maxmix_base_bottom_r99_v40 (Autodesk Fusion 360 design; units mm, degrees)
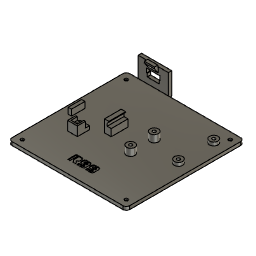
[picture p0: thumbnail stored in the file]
parameter "M2_SELF_TAP" = 1.85 comment "Hole size for self tapping M2"
sketch "Sketch1" plane through (0, 0, 0) normal (0, 0, 1) x axis (1, 0, 0)
  line L1 (33, 35) -> (-33, 35)
  line L2 (35, -33) -> (35, 33)
  line L3 (-33, -35) -> (33, -35)
  line L4 (-35, 33) -> (-35, -33)
  line L5 (0, 35) -> (0, -35)
  line L6 (35, 0) -> (-35, 0)
  arc A1 centre (-33, 33) radius 2 clockwise from (-35, 33) to (-33, 35)
  arc A2 centre (-33, -33) radius 2 clockwise from (-33, -35) to (-35, -33)
  arc A3 centre (33, -33) radius 2 clockwise from (35, -33) to (33, -35)
  arc A4 centre (33, 33) radius 2 clockwise from (33, 35) to (35, 33)
  point P2 (-35, 35)
  point P4 (-35, -35)
  point P3 (35, 35)
  point P17 (0, -35)
  point P18 (0, 35)
  point P19 (-35, 0)
  point P20 (35, 0)
  point P1 (0, 0)
  horizontal L1
  vertical L2
  horizontal L3
  vertical L4
  coincident P2 L1
  coincident P2 L4
  tangent L1 A1
  tangent L4 A1
  coincident P4 L4
  coincident P4 L3
  tangent L4 A2
  tangent L3 A2
  equal A1 A2
  tangent L3 A3
  tangent L2 A3
  equal A1 A3
  coincident P3 L1
  coincident P3 L2
  tangent L1 A4
  tangent L2 A4
  equal A1 A4
  midpoint L3 P17
  midpoint L1 P18
  midpoint L4 P19
  midpoint L2 P20
  coincident P1 L5
  coincident P1 L6
  dimension "d4" distance P2 P3 = 70
  dimension "d5" distance P2 P4 = 70
  dimension "d6" radius A1 = 2
extrude "Extrude1" new body sketch "Sketch1" profile of L1 L2 L3 L4 A1 A2 A3 A4 against normal blind 2
sketch "Sketch3" plane through (0, 0, -2) normal (0, 0, -1) x axis (1, 0, 0)
  line L1 (-33, 35) -> (33, 35)
  line L2 (-35, -33) -> (-35, 33)
  line L3 (33, -35) -> (-33, -35)
  line L4 (35, 33) -> (35, -33)
  line L5 (-30.9, -30.9) -> (30.9, -30.9)
  line L6 (-30.9, 30.9) -> (-30.9, -30.9)
  line L7 (30.9, 30.9) -> (-30.9, 30.9)
  line L8 (30.9, -30.9) -> (30.9, 30.9)
  line L9 (-30.9, 30.9) -> (30.9, -30.9)
  line L10 (30.9, 30.9) -> (-30.9, -30.9)
  arc A1 centre (33, 33) radius 2 clockwise from (33, 35) to (35, 33)
  arc A2 centre (-33, 33) radius 2 clockwise from (-35, 33) to (-33, 35)
  arc A3 centre (-33, -33) radius 2 clockwise from (-33, -35) to (-35, -33)
  arc A4 centre (33, -33) radius 2 clockwise from (35, -33) to (33, -35)
  point P18 (0, 0)
  point P1 (0, 0)
  point P16 (-30.9, 30.9)
  point P19 (-30.9, 30.9)
  point P17 (30.9, 30.9)
  point P20 (30.9, 30.9)
  point P14 (30.9, -30.9)
  point P21 (30.9, -30.9)
  point P15 (-30.9, -30.9)
  point P22 (-30.9, -30.9)
  horizontal L5
  perpendicular L5 L6
  parallel L5 L7
  parallel L6 L8
  coincident L9 P18
  coincident L10 P18
  coincident P1 P18
  coincident P16 P19
  coincident P17 P20
  coincident P14 P21
  coincident P15 P22
  dimension "d17" distance P16 P17 = 61.8
  dimension "d18" distance P15 P16 = 61.8
hole "Hole1" HoleDepth 2 HoleDiameter 2 TipAngle 118 CSDiameter 4.5 CSAngle 90
work_plane "WorkPlane1" AlongDistance -10
sketch "Sketch2" plane through (-10, 0, 0) normal (1, 0, 0) x axis (0, 1, 0)
  line L1 (35, -2) -> (35, 0)
  line L2 (35, 0) -> (35, -2)
  line L3 (35, 12) -> (35, 0)
  line L4 (37, 12) -> (35, 12)
  line L5 (37, -1) -> (37, 12)
  line L6 (36, -2) -> (37, -1)
  line L7 (35, -2) -> (36, -2)
  point P2 (35, 0)
  point P4 (35, 0)
  point P3 (35, -2)
  point P9 (35, -2)
  point P5 (35, 12)
  point P6 (37, 12)
  point P8 (36, -2)
  coincident P2 P4
  parallel L1 L3
  perpendicular L3 L4
  perpendicular L4 L5
  coincident P3 P9
  perpendicular L1 L7
  dimension "d10" distance P5 P6 = 2
  dimension "d11" distance P4 L4 = 12
  dimension "d12" angle L6 L7 = 45
  dimension "d13" distance L5 P8 = 1
extrude "Extrude2" add sketch "Sketch2" against normal blind 18
work_plane "WorkPlane2"
sketch "Sketch14" plane through (-19, 36, 5) normal (-1, 0, 0) x axis (0, 1, 0)
  line L1 (1, -7) -> (-1, -7)
  line L2 (-1, -7) -> (-1, 5)
  line L3 (-3.25, -7) -> (-1, -3.7867)
  line L4 (-3.25, -8) -> (-3.25, -7)
  line L5 (-1.25, -8) -> (-3.25, -8)
  line L6 (-1.25, -7) -> (-1.25, -8)
  line L7 (-1, -7) -> (-1.25, -7)
  point P5 (-1, -3.7867)
  point P2 (-1, -7)
  point P10 (-1, -7)
  point P6 (-3.25, -7)
  point P7 (-3.25, -8)
  point P8 (-1.25, -8)
  coincident L2 P5
  parallel L2 L4
  perpendicular L4 L5
  perpendicular L1 L6
  coincident P2 P10
  perpendicular L6 L7
  coincident P6 L7
  dimension "d109" = 3
  dimension "d110" distance P7 P8 = 2
  dimension "d111" distance P6 P7 = 1
  dimension "d112" distance L6 P10 = 0.25
  dimension "d115" angle L2 L3 = 35
extrude "Extrude18" add sketch "Sketch14" profile of L2 L3 L4 L5 L6 L7 distance 3
sketch "Sketch4" plane through (0, 37, 0) normal (0, 1, 0) x axis (-1, 0, 0)
  line L1 (10, -1) -> (10, 12)
  line L2 (28, -1) -> (10, -1)
  line L3 (28, 12) -> (28, -1)
  line L4 (10, 12) -> (28, 12)
  line L5 (10, -1) -> (10, 12)
  line L6 (10, -2) -> (10, -1)
  line L7 (28, -2) -> (10, -2)
  line L8 (28, -2) -> (28, -1)
  line L9 (28, -1) -> (28, 12)
  line L10 (28, 12) -> (10, 12)
  line L11 (15.025, 5.375) -> (15.025, 7.85)
  line L12 (15.425, 5.375) -> (15.025, 5.375)
  line L13 (15.425, 3.5) -> (15.425, 5.375)
  line L14 (22.575, 3.5) -> (15.425, 3.5)
  line L15 (22.575, 5.375) -> (22.575, 3.5)
  line L16 (22.975, 5.375) -> (22.575, 5.375)
  line L17 (22.975, 7.85) -> (22.975, 5.375)
  line L18 (15.025, 7.85) -> (22.975, 7.85)
  line L19 (19, 12) -> (19, -2)
  line L20 (10, 0) -> (28, 0)
  point P20 (19, -2)
  point P21 (19, 12)
  point P12 (15.025, 7.85)
  point P19 (22.975, 7.85)
  point P15 (15.425, 3.5)
  point P16 (22.575, 3.5)
  vertical L11
  perpendicular L11 L12
  perpendicular L12 L13
  perpendicular L13 L14
  perpendicular L14 L15
  perpendicular L15 L16
  perpendicular L16 L17
  perpendicular L11 L18
  midpoint L7 P20
  midpoint L10 P21
  symmetric L11 L17 L19
  symmetric L13 L15 L19
  collinear L12 L16
  dimension "d26" distance P12 P19 = 7.95
  dimension "d27" distance P15 P16 = 7.15
  dimension "d29" distance L14 L18 = 4.35
  dimension "d30" distance L12 L18 = 2.475
  dimension "d102" distance L14 L20 = 3.5
extrude "Extrude3" cut sketch "Sketch4" profile of L11 L12 L13 L14 L15 L16 L17 L18 no distance stored
sketch "Sketch5" plane through (0, 0, 0) normal (0, 0, 1) x axis (-1, 0, 0)
  line L1 (-35, -33) -> (-35, 33)
  line L2 (10, -35) -> (-33, -35)
  line L3 (28, -35) -> (10, -35)
  line L4 (33, -35) -> (28, -35)
  line L5 (35, 33) -> (35, -33)
  line L6 (-33, 35) -> (33, 35)
  line L7 (-27.5, -3.5) -> (-27.5, -24.5)
  circle C1 centre (-30.9, 30.9) radius 1
  circle C2 centre (30.9, -30.9) radius 1
  circle C3 centre (-30.9, -30.9) radius 1
  circle C4 centre (30.9, 30.9) radius 1
  arc A1 centre (-33, 33) radius 2 clockwise from (-35, 33) to (-33, 35)
  arc A2 centre (-33, -33) radius 2 clockwise from (-33, -35) to (-35, -33)
  arc A3 centre (33, -33) radius 2 clockwise from (35, -33) to (33, -35)
  arc A4 centre (33, 33) radius 2 clockwise from (33, 35) to (35, 33)
  circle C5 centre (-27.5, -24.5) radius 2.5
  circle C6 centre (-27.5, -3.5) radius 2.5
  circle C7 centre (-27.5, -3.5) radius 0.925
  circle C8 centre (-27.5, -24.5) radius 0.925
  point P20 (-27.5, -24.5)
  point P22 (-27.5, -24.5)
  point P21 (-27.5, -3.5)
  point P23 (-27.5, -3.5)
  point P1 (0, 0)
  vertical L7
  coincident P20 P22
  coincident P21 P23
  equal C5 C6
  concentric C6 C7
  concentric C5 C8
  equal C7 C8
  dimension "d32" distance P1 L7 = 27.5
  dimension "d33" distance P20 P21 = 21
  dimension "d34" distance P1 P21 = 3.5
  dimension "d35" diameter C6 = 5
  dimension "d36" diameter C7 = 1.85 (= "M2_SELF_TAP")
extrude "Extrude4" add sketch "Sketch5" profile of C5 C6 C7 C8 along normal blind 2
sketch "Sketch6" plane through (0, 0, 0) normal (0, 0, 1) x axis (-1, 0, 0)
  line L1 (-35, -33) -> (-35, 33)
  line L2 (10, -35) -> (-33, -35)
  line L3 (28, -35) -> (10, -35)
  line L4 (33, -35) -> (28, -35)
  line L5 (35, 33) -> (35, -33)
  line L6 (-33, 35) -> (33, 35)
  line L7 (28.4, -3.8) -> (30.4, -3.8)
  line L8 (28.4, 4.2) -> (28.4, -3.8)
  line L9 (30.4, 4.2) -> (28.4, 4.2)
  line L10 (30.4, -3.8) -> (30.4, 4.2)
  line L11 (10, -7) -> (6, -7)
  line L12 (10, 3) -> (10, -7)
  line L13 (6, 3) -> (10, 3)
  line L14 (6, -7) -> (6, 3)
  line L15 (16.1, 5.8) -> (21.9, 5.8)
  line L16 (16.1, 13) -> (16.1, 5.8)
  line L17 (21.9, 13) -> (16.1, 13)
  line L18 (21.9, 5.8) -> (21.9, 13)
  line L19 (16.1, 8.2) -> (21.9, 8.2)
  line L20 (20.9, 12) -> (20.9, 8.2)
  line L21 (17.1, 12) -> (20.9, 12)
  line L22 (17.1, 8.2) -> (17.1, 12)
  line L23 (17.1, 10.1) -> (20.9, 10.1)
  line L24 (19, 12) -> (19, 8.2)
  circle C1 centre (-27.5, -3.5) radius 2.5
  circle C2 centre (-30.9, 30.9) radius 1
  circle C3 centre (30.9, -30.9) radius 1
  circle C4 centre (-30.9, -30.9) radius 1
  circle C5 centre (30.9, 30.9) radius 1
  arc A1 centre (-33, 33) radius 2 clockwise from (-35, 33) to (-33, 35)
  arc A2 centre (-33, -33) radius 2 clockwise from (-33, -35) to (-35, -33)
  arc A3 centre (33, -33) radius 2 clockwise from (35, -33) to (33, -35)
  arc A4 centre (33, 33) radius 2 clockwise from (33, 35) to (35, 33)
  circle C6 centre (-27.5, -24.5) radius 2.5
  circle C7 centre (19, 10.1) radius 0.925
  point P34 (21.9, 8.2)
  point P35 (16.1, 8.2)
  point P36 (20.9, 8.2)
  point P39 (17.1, 8.2)
  point P40 (20.9, 10.1)
  point P41 (17.1, 10.1)
  point P42 (19, 8.2)
  point P43 (19, 12)
  point P44 (19, 10.1)
  point P1 (0, 0)
  point P24 (28.4, 4.2)
  point P22 (30.4, -3.8)
  point P23 (28.4, -3.8)
  point P25 (30.4, 4.2)
  point P26 (6, -7)
  point P27 (10, -7)
  point P28 (10, 3)
  point P32 (16.1, 13)
  point P33 (21.9, 13)
  point P30 (21.9, 5.8)
  horizontal L7
  vertical L8
  horizontal L9
  vertical L10
  horizontal L11
  vertical L12
  horizontal L13
  vertical L14
  horizontal L15
  vertical L16
  horizontal L17
  vertical L18
  coincident L18 P34
  coincident L16 P35
  perpendicular L16 L19
  coincident L19 P36
  perpendicular L19 L20
  perpendicular L20 L21
  coincident L19 P39
  perpendicular L19 L22
  midpoint L20 P40
  midpoint L22 P41
  midpoint L19 P42
  midpoint L21 P43
  midpoint L23 P44
  dimension "d39" distance P1 P24 = 28.4
  dimension "d40" distance P1 P24 = 4.2
  dimension "d41" distance P22 P23 = 2
  dimension "d42" distance P22 P25 = 8
  dimension "d43" distance P1 L14 = 6
  dimension "d44" distance P1 P26 = 7
  dimension "d45" distance P26 P27 = 4
  dimension "d46" distance P27 P28 = 10
  dimension "d47" distance P1 L16 = 16.1
  dimension "d48" distance P1 L15 = 5.8
  dimension "d49" distance P32 P33 = 5.8
  dimension "d50" distance P30 P33 = 7.2
  dimension "d51" distance L15 L19 = 2.4
  dimension "d52" distance L16 L22 = 1
  dimension "d53" distance L18 L20 = 1 (= "d52")
  dimension "d54" distance L17 L21 = 1 (= "d52")
  dimension "d55" diameter C7 = 1.85 (= "M2_SELF_TAP")
  dimension "d124" distance L8 L12 = 18.4
extrude "Extrude5" add sketch "Sketch6" profile of L7 L8 L9 L10 L11 L12 L13 L14 along normal blind 3.6
extrude "Extrude6" add sketch "Sketch6" profile of L11 L13 L14 L15 L16 L18 L19 along normal blind 2
extrude "Extrude7" add sketch "Sketch6" profile of L19 L20 L21 L22 C7 along normal blind 3.5
extrude "Extrude8" add sketch "Sketch6" profile of L16 L17 L18 L19 L20 L21 L22 along normal blind 5.5
sketch "Sketch7" plane through (0, 0, 0) normal (0, 0, 1) x axis (-1, 0, 0)
  line L1 (16.1, 13) -> (16.1, 5.8)
  line L2 (21.9, 13) -> (16.1, 13)
  line L3 (21.9, 5.8) -> (21.9, 13)
  line L4 (16.1, 5.8) -> (21.9, 5.8)
  line L5 (-35, -33) -> (-35, 33)
  line L6 (10, -35) -> (-33, -35)
  line L7 (28, -35) -> (10, -35)
  line L8 (33, -35) -> (28, -35)
  line L9 (35, 33) -> (35, -33)
  line L10 (-33, 35) -> (33, 35)
  line L11 (30.4, -3.8) -> (30.4, 4.2)
  line L12 (28.4, -3.8) -> (30.4, -3.8)
  line L13 (28.4, 4.2) -> (28.4, -3.8)
  line L14 (30.4, 4.2) -> (28.4, 4.2)
  line L15 (6, -7) -> (10, -7)
  line L16 (6, 3) -> (6, -7)
  line L17 (10, 3) -> (6, 3)
  line L18 (10, -7) -> (10, 3)
  line L19 (-8.65, 6.5) -> (-8.65, -10.5)
  line L20 (6, -7) -> (6, 3)
  line L21 (10, -7) -> (6, -7)
  line L22 (10, 3) -> (10, -7)
  line L23 (6, 3) -> (10, 3)
  line L24 (8.25, 3) -> (8.25, -7)
  circle C1 centre (-27.5, -24.5) radius 2.5
  arc A1 centre (-33, 33) radius 2 clockwise from (-35, 33) to (-33, 35)
  arc A2 centre (-33, -33) radius 2 clockwise from (-33, -35) to (-35, -33)
  arc A3 centre (33, -33) radius 2 clockwise from (35, -33) to (33, -35)
  arc A4 centre (33, 33) radius 2 clockwise from (33, 35) to (35, 33)
  circle C2 centre (30.9, 30.9) radius 1
  circle C3 centre (-30.9, -30.9) radius 1
  circle C4 centre (30.9, -30.9) radius 1
  circle C5 centre (-30.9, 30.9) radius 1
  circle C6 centre (-27.5, -3.5) radius 2.5
  circle C7 centre (-8.65, -10.5) radius 2.5
  circle C8 centre (-8.65, 6.5) radius 2.5
  circle C9 centre (-8.65, -10.5) radius 0.925
  circle C10 centre (-8.65, 6.5) radius 0.925
  point P34 (-8.65, -10.5)
  point P38 (-8.65, -10.5)
  point P37 (-8.65, 6.5)
  point P39 (-8.65, 6.5)
  point P44 (8.25, -7)
  point P45 (8.25, 3)
  point P1 (0, 0)
  point P36 (-8.65, -10.5)
  equal C7 C8
  concentric C7 C9
  concentric C8 C10
  equal C9 C10
  coincident P34 P38
  coincident P37 P39
  vertical L19
  coincident L15 P44
  coincident L17 P45
  perpendicular L17 L24
  dimension "d65" distance P1 P34 = 10.5
  dimension "d67" diameter C7 = 5
  dimension "d68" diameter C9 = 1.85 (= "M2_SELF_TAP")
  dimension "d72" distance P36 P37 = 17
  dimension "d73" distance P1 L19 = 8.65
  dimension "d127" distance P36 L24 = 16.9
extrude "Extrude9" add sketch "Sketch7" profile of C7 C8 C9 C10 along normal blind 2
extrude "Extrude19" sketch "Sketch7" profile of L15 L16 L17 L20 L21 L23 L24 no distance stored
sketch "Sketch20" plane through (0, -3, 0) normal (0, -1, 0) x axis (1, 0, 0)
  line L1 (-8.25, 2) -> (-6, 2)
  line L2 (-8.25, 3.6) -> (-8.25, 2)
  line L3 (-10, 3.6) -> (-8.25, 3.6)
  line L4 (-10, 0) -> (-10, 3.6)
  line L5 (-6, 0) -> (-10, 0)
  line L6 (-6, 2) -> (-6, 0)
  line L7 (-8.25, 3.6) -> (-10, 3.6)
  line L8 (-7.25, 4.6) -> (-8.25, 3.6)
  line L9 (-10, 3.6) -> (-10, 5)
  line L10 (-7.25, 5) -> (-7.25, 4.6)
  line L11 (-10, 5) -> (-7.25, 5)
  point P4 (-8.25, 3.6)
  point P10 (-8.25, 3.6)
  point P8 (-10, 3.6)
  point P13 (-10, 3.6)
  point P12 (-10, 5)
  point P15 (-10, 5)
  point P11 (-7.25, 4.6)
  coincident P4 P10
  coincident P8 P13
  vertical L9
  vertical L10
  perpendicular L10 L11
  coincident P12 P15
  dimension "d135" angle L7 L8 = 135
  dimension "d140" distance P10 P11 = 1
  dimension "d141" distance P11 L11 = 0.4
extrude "Extrude21" add sketch "Sketch20" profile of L3 L7 L8 L9 to an object
sketch "Sketch9" plane through (0, 0, 0) normal (0, 0, 1) x axis (1, 0, 0)
  line L1 (8.2, 8.4) -> (8.2, -5.6)
  circle C1 centre (8.2, -5.6) radius 2.5
  circle C2 centre (8.2, 8.4) radius 2.5
  circle C3 centre (8.2, 8.4) radius 0.925
  circle C4 centre (8.2, -5.6) radius 0.925
  point P3 (8.2, 8.4)
  point P4 (8.2, 8.4)
  point P2 (8.2, -5.6)
  point P6 (8.2, -5.6)
  point P7 (8.2, 8.4)
  point P1 (0, 0)
  equal C1 C2
  concentric C1 C4
  equal C3 C4
  coincident P3 P4
  coincident P2 P6
  coincident P4 P7
  vertical L1
  dimension "d81" distance P2 P3 = 14
  dimension "d82" distance P1 P2 = 5.6
  dimension "d83" diameter C2 = 5
  dimension "d84" diameter C3 = 1.85 (= "M2_SELF_TAP")
  dimension "d89" distance P1 L1 = 8.2
extrude "Extrude11" add sketch "Sketch9" profile of C1 C2 C3 C4 along normal blind 4.2
sketch "Sketch10" plane through (0, 0, 2) normal (0, 0, 1) x axis (-1, 0, 0)
  line L1 (21.9, 8.2) -> (21.9, 5.8)
  line L2 (16.1, 8.2) -> (21.9, 8.2)
  line L3 (16.1, 5.8) -> (16.1, 8.2)
  line L4 (21.9, 5.8) -> (16.1, 5.8)
sketch "Sketch11" plane through (0, 0, 3.6) normal (0, 0, 1) x axis (-1, 0, 0)
  line L1 (10, 3) -> (10, -7)
  line L2 (6, 3) -> (10, 3)
  line L3 (10, -7) -> (6, -7)
  line L4 (8.4, 3) -> (8.4, -7)
  line L5 (6, -7) -> (6, 3)
  circle C1 centre (-8.2, -8.4) radius 0.925
  circle C2 centre (-8.2, 5.6) radius 0.925
  point P8 (8.4, -7)
  point P9 (8.4, 3)
  point P6 (-8.2, -8.4)
  coincident L3 P8
  coincident L2 P9
  perpendicular L2 L4
  dimension "d90" distance P6 L4 = 16.6
extrude "Extrude14" sketch "Sketch11" profile of L1 L2 L3 L4 blind 1.6 Side2Offset 0
extrude "Extrude20" add of existing geometry to an object
sketch "Sketch21" plane through (0, -3, 0) normal (0, -1, 0) x axis (1, 0, 0)
  line L1 (-6, 4.2) -> (-6, 0)
  line L2 (-8.4, 4.2) -> (-6, 4.2)
  line L3 (-8.4, 5.8) -> (-8.4, 4.2)
  line L4 (-10, 5.8) -> (-8.4, 5.8)
  line L5 (-10, 0) -> (-10, 5.8)
  line L6 (-6, 0) -> (-10, 0)
  line L7 (-8.4, 5.8) -> (-10, 5.8)
  line L8 (-7.4, 6.8) -> (-8.4, 5.8)
  line L9 (-7.4, 7.2) -> (-7.4, 6.8)
  line L10 (-10, 7.2) -> (-7.4, 7.2)
  line L11 (-10, 5.8) -> (-10, 7.2)
  point P9 (-8.4, 5.8)
  point P10 (-8.4, 5.8)
  point P6 (-10, 5.8)
  point P14 (-10, 5.8)
  point P11 (-7.4, 6.8)
  coincident P9 P10
  perpendicular L4 L9
  perpendicular L9 L10
  coincident P6 P14
  perpendicular L7 L11
  dimension "d142" angle L7 L8 = 135
  dimension "d143" distance L7 P11 = 1
  dimension "d144" distance P11 L10 = 0.4
extrude "Extrude22" add sketch "Sketch21" profile of L4 L7 L8 L9 L10 L11 to an object
sketch "Sketch8" plane through (0, 0, 0) normal (0, 0, 1) x axis (-1, 0, 0)
  line L1 (16.1, 13) -> (16.1, 5.8)
  line L2 (21.9, 13) -> (16.1, 13)
  line L3 (21.9, 5.8) -> (21.9, 13)
  line L4 (16.1, 5.8) -> (21.9, 5.8)
  line L5 (-35, -33) -> (-35, 33)
  line L6 (10, -35) -> (-33, -35)
  line L7 (28, -35) -> (10, -35)
  line L8 (33, -35) -> (28, -35)
  line L9 (35, 33) -> (35, -33)
  line L10 (-33, 35) -> (33, 35)
  line L11 (30.4, -3.8) -> (30.4, 4.2)
  line L12 (28.4, -3.8) -> (30.4, -3.8)
  line L13 (28.4, 4.2) -> (28.4, -3.8)
  line L14 (30.4, 4.2) -> (28.4, 4.2)
  line L15 (6, -7) -> (10, -7)
  line L16 (6, 3) -> (6, -7)
  line L17 (10, 3) -> (6, 3)
  line L18 (10, -7) -> (10, 3)
  curve K1 (-7.2736, 27.5) -> (7.2693, 27.5)
  curve K2 (-7.2736, 19.5) -> (-7.2736, 27.5)
  curve K3 (7.2693, 19.5) -> (-7.2736, 19.5)
  curve K4 (7.2693, 27.5) -> (7.2693, 19.5)
  line L19 (0, 35) -> (0, 0)
  circle C1 centre (-27.5, -24.5) radius 2.5
  arc A1 centre (-33, 33) radius 2 clockwise from (-35, 33) to (-33, 35)
  arc A2 centre (-33, -33) radius 2 clockwise from (-33, -35) to (-35, -33)
  arc A3 centre (33, -33) radius 2 clockwise from (35, -33) to (33, -35)
  arc A4 centre (33, 33) radius 2 clockwise from (33, 35) to (35, 33)
  circle C2 centre (30.9, 30.9) radius 1
  circle C3 centre (-30.9, -30.9) radius 1
  circle C4 centre (30.9, -30.9) radius 1
  circle C5 centre (-30.9, 30.9) radius 1
  circle C6 centre (-27.5, -3.5) radius 2.5
  circle C7 centre (-8.2, -8.4) radius 2.5
  circle C8 centre (-8.2, 5.6) radius 2.5
  point P1 (0, 0)
  point P38 (0, 0)
  point P39 (0, 35)
  perpendicular K1 K2
  parallel K1 K3
  parallel K2 K4
  horizontal K3
  coincident P1 P38
  midpoint L10 P39
  dimension "d78" distance P1 K1 = 27.5
extrude "Extrude10" cut sketch "Sketch8" against normal blind 0.4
